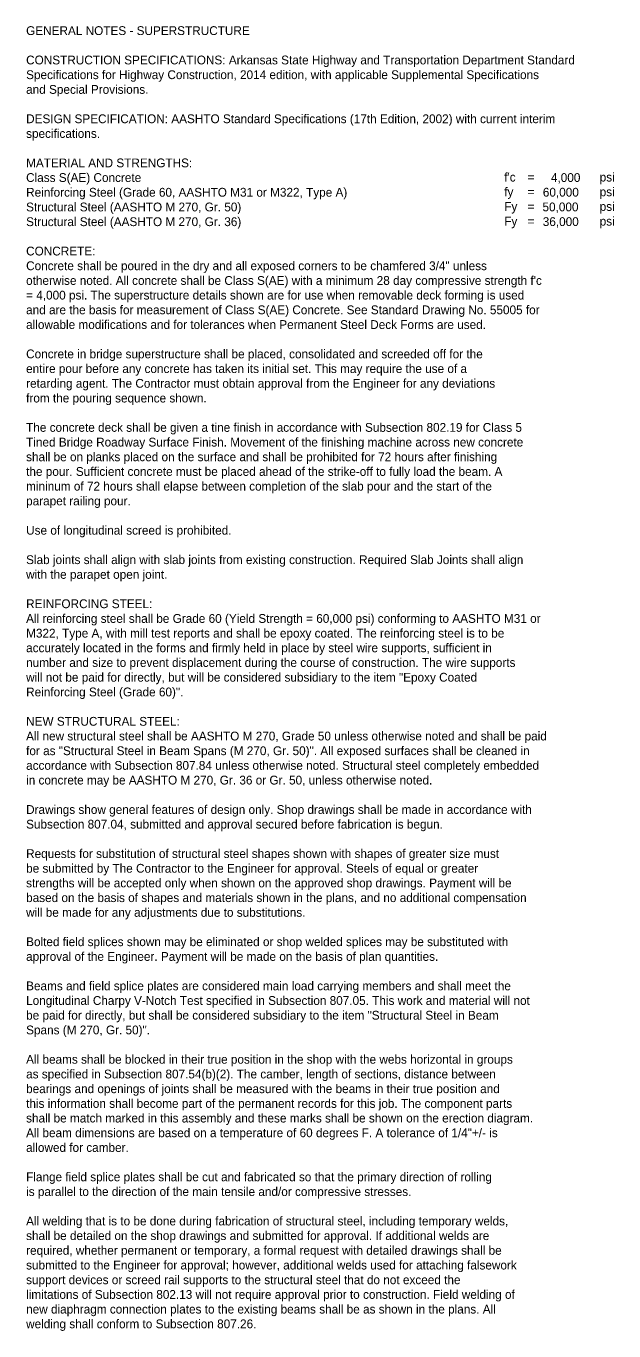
# Model space of a CAD drawing. Extents: x -30245.5 to -30215, y 5204.9 to 5224.7.
# Drawn here: x -30245.5 to -30237.15, y 5206.12 to 5224.66 of the extents above; entities that cross this region are included whole.
import ezdxf

# ---------------------------------------------------------------- set-up
doc = ezdxf.new("R2010")
doc.units = 0
doc.layers.add('B_Text', color=7, linetype='Continuous')

msp = doc.modelspace()

# ---------------------------------------------------------------- texts
at = {"layer": 'B_Text'}
for s, p in [('GENERAL NOTES - SUPERSTRUCTURE', (-30245.501, 5224.529)), ('CONSTRUCTION SPECIFICATIONS: Arkansas State Highway and Transportation Department Standard ', (-30245.501, 5224.112)), ('Specifications for Highway Construction, 2014 edition, with applicable Supplemental Specifications ', (-30245.501, 5223.903)), ('and Special Provisions.', (-30245.501, 5223.694)), ('DESIGN SPECIFICATION: AASHTO Standard Specifications (17th Edition, 2002) with current interim ', (-30245.501, 5223.277)), ('specifications.', (-30245.501, 5223.068)), ('MATERIAL AND STRENGTHS:', (-30245.501, 5222.65)), ('Class S(AE) Concrete', (-30245.501, 5222.442)), ("f'c", (-30238.71, 5222.448)), ('=', (-30238.379, 5222.448)), ('4,000', (-30238.047, 5222.442)), ('psi', (-30237.355, 5222.448)), ('Reinforcing Steel (Grade 60, AASHTO M31 or M322, Type A)', (-30245.501, 5222.233)), ('fy', (-30238.71, 5222.239)), ('=', (-30238.379, 5222.239)), ('60,000', (-30238.162, 5222.234)), ('psi', (-30237.355, 5222.239)), ('Structural Steel (AASHTO M 270, Gr. 50)', (-30245.501, 5222.024)), ('Fy', (-30238.71, 5222.031)), ('=', (-30238.379, 5222.031)), ('50,000', (-30238.167, 5222.025)), ('psi', (-30237.355, 5222.031)), ('Structural Steel (AASHTO M 270, Gr. 36)', (-30245.501, 5221.815)), ('Fy', (-30238.71, 5221.822)), ('36,000', (-30238.163, 5221.816)), ('psi', (-30237.355, 5221.822)), ('=', (-30238.379, 5221.822)), ('CONCRETE:', (-30245.501, 5221.398)), ('Concrete shall be poured in the dry and all exposed corners to be chamfered 3/4" unless ', (-30245.501, 5221.189)), ("otherwise noted. All concrete shall be Class S(AE) with a minimum 28 day compressive strength f'c ", (-30245.501, 5220.98)), ('= 4,000 psi. The superstructure details shown are for use when removable deck forming is used ', (-30245.501, 5220.772)), ('and are the basis for measurement of Class S(AE) Concrete. See Standard Drawing No. 55005 for ', (-30245.501, 5220.563)), ('allowable modifications and for tolerances when Permanent Steel Deck Forms are used.', (-30245.501, 5220.354)), ('Concrete in bridge superstructure shall be placed, consolidated and screeded off for the ', (-30245.501, 5219.937)), ('entire pour before any concrete has taken its initial set. This may require the use of a ', (-30245.501, 5219.728)), ('retarding agent. The Contractor must obtain approval from the Engineer for any deviations ', (-30245.501, 5219.519)), ('from the pouring sequence shown.', (-30245.501, 5219.31)), ('The concrete deck shall be given a tine finish in accordance with Subsection 802.19 for Class 5 ', (-30245.501, 5218.893)), ('Tined Bridge Roadway Surface Finish. Movement of the finishing machine across new concrete ', (-30245.501, 5218.684)), ('shall be on planks placed on the surface and shall be prohibited for 72 hours after finishing ', (-30245.501, 5218.475)), ('the pour. Sufficient concrete must be placed ahead of the strike-off to fully load the beam. A ', (-30245.501, 5218.267)), ('mininum of 72 hours shall elapse between completion of the slab pour and the start of the ', (-30245.501, 5218.058)), ('parapet railing pour.', (-30245.501, 5217.849)), ('Use of longitudinal screed is prohibited. ', (-30245.501, 5217.432)), ('Slab joints shall align with slab joints from existing construction. Required Slab Joints shall align ', (-30245.501, 5217.014)), ('with the parapet open joint.', (-30245.501, 5216.805)), ('REINFORCING STEEL:', (-30245.501, 5216.388)), ('All reinforcing steel shall be Grade 60 (Yield Strength = 60,000 psi) conforming to AASHTO M31 or ', (-30245.501, 5216.179)), ('M322, Type A, with mill test reports and shall be epoxy coated. The reinforcing steel is to be ', (-30245.501, 5215.97)), ('accurately located in the forms and firmly held in place by steel wire supports, sufficient in ', (-30245.501, 5215.762)), ('number and size to prevent displacement during the course of construction. The wire supports ', (-30245.501, 5215.553)), ('will not be paid for directly, but will be considered subsidiary to the item "Epoxy Coated ', (-30245.501, 5215.344)), ('Reinforcing Steel (Grade 60)".', (-30245.501, 5215.135)), ('NEW STRUCTURAL STEEL:', (-30245.501, 5214.718)), ('All new structural steel shall be AASHTO M 270, Grade 50 unless otherwise noted and shall be paid ', (-30245.501, 5214.509)), ('for as "Structural Steel in Beam Spans (M 270, Gr. 50)". All exposed surfaces shall be cleaned in ', (-30245.501, 5214.3)), ('accordance with Subsection 807.84 unless otherwise noted. Structural steel completely embedded ', (-30245.501, 5214.092)), ('in concrete may be AASHTO M 270, Gr. 36 or Gr. 50, unless otherwise noted.', (-30245.501, 5213.883)), ('Drawings show general features of design only. Shop drawings shall be made in accordance with ', (-30245.501, 5213.465)), ('Subsection 807.04, submitted and approval secured before fabrication is begun.', (-30245.501, 5213.257)), ('Requests for substitution of structural steel shapes shown with shapes of greater size must ', (-30245.501, 5212.839)), ('be submitted by The Contractor to the Engineer for approval. Steels of equal or greater ', (-30245.501, 5212.63)), ('strengths will be accepted only when shown on the approved shop drawings. Payment will be ', (-30245.501, 5212.422)), ('based on the basis of shapes and materials shown in the plans, and no additional compensation ', (-30245.501, 5212.213)), ('will be made for any adjustments due to substitutions.', (-30245.501, 5212.004)), ('Bolted field splices shown may be eliminated or shop welded splices may be substituted with ', (-30245.501, 5211.587)), ('approval of the Engineer. Payment will be made on the basis of plan quantities.', (-30245.501, 5211.378)), ('Beams and field splice plates are considered main load carrying members and shall meet the ', (-30245.501, 5210.96)), ('Longitudinal Charpy V-Notch Test specified in Subsection 807.05. This work and material will not ', (-30245.501, 5210.752)), ('be paid for directly, but shall be considered subsidiary to the item "Structural Steel in Beam ', (-30245.501, 5210.543)), ('Spans (M 270, Gr. 50)".', (-30245.501, 5210.334)), ('All beams shall be blocked in their true position in the shop with the webs horizontal in groups ', (-30245.501, 5209.917)), ('as specified in Subsection 807.54(b)(2). The camber, length of sections, distance between ', (-30245.501, 5209.708)), ('bearings and openings of joints shall be measured with the beams in their true position and ', (-30245.501, 5209.499)), ('this information shall become part of the permanent records for this job. The component parts ', (-30245.501, 5209.29)), ('shall be match marked in this assembly and these marks shall be shown on the erection diagram. ', (-30245.501, 5209.082)), ('All beam dimensions are based on a temperature of 60 degrees F. A tolerance of 1/4"+/- is ', (-30245.501, 5208.873)), ('allowed for camber.', (-30245.501, 5208.664)), ('Flange field splice plates shall be cut and fabricated so that the primary direction of rolling ', (-30245.501, 5208.247)), ('is parallel to the direction of the main tensile and/or compressive stresses.', (-30245.501, 5208.038)), ('All welding that is to be done during fabrication of structural steel, including temporary welds, ', (-30245.501, 5207.62)), ('shall be detailed on the shop drawings and submitted for approval. If additional welds are ', (-30245.501, 5207.412)), ('required, whether permanent or temporary, a formal request with detailed drawings shall be ', (-30245.501, 5207.203)), ('submitted to the Engineer for approval; however, additional welds used for attaching falsework ', (-30245.501, 5206.994)), ('support devices or screed rail supports to the structural steel that do not exceed the ', (-30245.501, 5206.785)), ('limitations of Subsection 802.13 will not require approval prior to construction. Field welding of ', (-30245.501, 5206.577)), ('new diaphragm connection plates to the existing beams shall be as shown in the plans. All ', (-30245.501, 5206.368)), ('welding shall conform to Subsection 807.26.', (-30245.501, 5206.159))]:
    msp.add_text(s, height=0.125, dxfattribs=at).set_placement(p)

doc.saveas('drawing.dxf')
